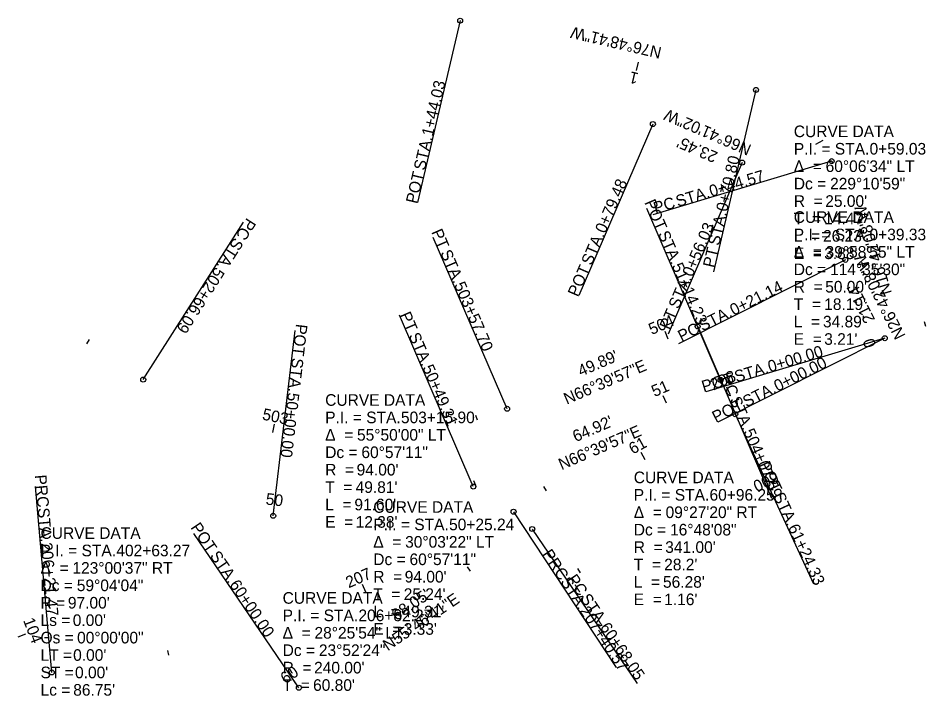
# Model space of a CAD drawing. Extents: x 1600023 to 1602131, y 285824 to 287284.
# Drawn here: x 1601005.3 to 1601224.1, y 286686.3 to 286849.7 of the extents above; entities that cross this region are included whole.
import ezdxf

# ---------------------------------------------------------------- set-up
doc = ezdxf.new("R2010")
doc.units = 0
for name, color, linetype in [('_CIVIL_CONSTRUCTION', 7, 'Continuous'), ('Default', 7, 'Continuous'), ('GE_P_Alignment', 7, 'Continuous'), ('PF_P_Grade_Line', 7, 'Continuous'), ('PF_X_Ground_Line', 7, 'Continuous'), ('SC_Scratch6', 7, 'Continuous'), ('SC_Scratch7', 7, 'Continuous')]:
    doc.layers.add(name, color=color, linetype=linetype)

msp = doc.modelspace()

# ---------------------------------------------------------------- linework, layer by layer
at = {"layer": '_CIVIL_CONSTRUCTION'}
for p, q in [((1601158.26, 286824.15), (1601140.44, 286782.82)), ((1601179.79, 286814.87), (1601161.98, 286773.54)), ((1601204.67, 286791.42), (1601164.47, 286771.2)), ((1601214.17, 286772.53), (1601173.96, 286752.31)), ((1601013.35, 286691.95), (1601009.45, 286736.78)), ((1601124.67, 286730.7), (1601149.45, 286693.13))]:
    msp.add_line(p, q, dxfattribs=at)
for centre in [(1601158.26, 286824.15), (1601179.79, 286814.87), (1601204.67, 286791.42), (1601214.17, 286772.53), (1601124.67, 286730.7), (1601013.35, 286691.95)]:
    msp.add_circle(centre, 0.6, dxfattribs=at)
at = {"layer": 'Default'}
for p, q in [((1601174.59, 286762.47), (1601156.77, 286803.79)), ((1601035.4, 286762.56), (1601059.57, 286800.51)), ((1601123.13, 286755.52), (1601105.31, 286796.84)), ((1601208.96, 286789.65), (1601208.62, 286790.8)), ((1601114.98, 286736.76), (1601097.15, 286778.08)), ((1601169.07, 286775.34), (1601186.88, 286734.01)), ((1601066.74, 286729.72), (1601072.01, 286774.41)), ((1601161.98, 286772.28), (1601161.19, 286774.12)), ((1601021.82, 286771.2), (1601022.47, 286772.22)), ((1601161.52, 286756.84), (1601160.73, 286758.67)), ((1601115.95, 286752.77), (1601115.57, 286753.9)), ((1601178.12, 286754.21), (1601196.97, 286713.35)), ((1601066.63, 286749.83), (1601067.04, 286751.79)), ((1601156.41, 286743.24), (1601155.45, 286745)), ((1601183.71, 286741.37), (1601184.55, 286739.56)), ((1601115.61, 286737.03), (1601115.14, 286738.13)), ((1601066.74, 286729.72), (1601066.98, 286731.7)), ((1601129.19, 286726.54), (1601154.5, 286689.33)), ((1601072.92, 286688.27), (1601047.62, 286725.48)), ((1601114.27, 286716.39), (1601113.59, 286717.38)), ((1601140.1, 286717), (1601140.77, 286716)), ((1601072.92, 286688.27), (1601071.8, 286689.92))]:
    msp.add_line(p, q, dxfattribs=at)
for centre in [(1601169.07, 286775.34), (1601035.4, 286762.56), (1601174.59, 286762.47), (1601123.13, 286755.52), (1601178.12, 286754.21), (1601114.98, 286736.76), (1601066.74, 286729.72), (1601129.19, 286726.54), (1601072.92, 286688.27)]:
    msp.add_circle(centre, 0.6, dxfattribs=at)
at = {"layer": 'SC_Scratch6'}
for p, q in [((1601224.07, 286775.34), (1601223.76, 286776.5)), ((1601176.89, 286758.93), (1601176.09, 286760.77)), ((1601132.62, 286735.78), (1601131.99, 286736.8)), ((1601089.09, 286711.32), (1601088.28, 286713.15)), ((1601005.25, 286700.58), (1601007.12, 286701.3)), ((1601041.56, 286696.1), (1601041.31, 286697.28))]:
    msp.add_line(p, q, dxfattribs=at)
at = {"layer": 'SC_Scratch7'}
for p, q in [((1601111.81, 286849.09), (1601101.55, 286805.27)), ((1601154.68, 286839.04), (1601154.23, 286837.09)), ((1601183.12, 286832.38), (1601172.85, 286788.57)), ((1601199.25, 286820.22), (1601197.5, 286819.24)), ((1601201.36, 286815.22), (1601158.26, 286802.29)), ((1601214.17, 286772.53), (1601171.06, 286759.6)), ((1601214.17, 286772.53), (1601212.25, 286771.96))]:
    msp.add_line(p, q, dxfattribs=at)
for centre in [(1601111.81, 286849.09), (1601183.12, 286832.38), (1601201.36, 286815.22), (1601214.17, 286772.53)]:
    msp.add_circle(centre, 0.6, dxfattribs=at)

# ---------------------------------------------------------------- texts
at = {"layer": '_CIVIL_CONSTRUCTION'}
for s, rotation, p in [('0+79.48', 66.684, (1601146.78, 286797.63)), ('0+56.03', 66.684, (1601167.79, 286787.12)), (' STA. ', 66.684, (1601143.04, 286788.95)), ('POT', 66.684, (1601140.19, 286782.33)), (' STA. ', 66.684, (1601164.04, 286778.44)), ('0+21.14', 26.7021, (1601177.72, 286777.91)), ('PT', 66.684, (1601162.3, 286774.39)), (' STA. ', 26.7021, (1601169.27, 286773.66)), ('PC', 26.7021, (1601165.18, 286771.6)), ('0+00.00', 26.7021, (1601188.32, 286759.58)), (' STA. ', 26.7021, (1601179.88, 286755.33)), ('POT', 26.7021, (1601173.44, 286752.1)), ('PRC', 274.977, (1601009.25, 286739.51)), (' STA. ', 274.977, (1601009.85, 286732.59)), ('206+21.47', 274.977, (1601010.67, 286723.18)), ('PRC', 303.4087, (1601131.46, 286720.49)), (' STA. ', 303.4087, (1601135.28, 286714.69)), ('207+40.57', 303.4087, (1601140.49, 286706.8))]:
    msp.add_text(s, height=2.8, rotation=rotation, dxfattribs=at).set_placement(p)
at = {"layer": 'Default'}
for s, rotation, p in [('POT', 293.3341, (1601156.17, 286805.28)), ('PC', 237.5008, (1601060.4, 286801.72)), ('PT', 293.3341, (1601104.79, 286798.15)), (' STA. ', 237.5008, (1601057.93, 286797.85)), (' STA. ', 293.3341, (1601159.02, 286798.67)), (' STA. ', 293.3341, (1601106.54, 286794.1)), ('51+14.23', 293.3341, (1601162.76, 286789.99)), ('502+66.09', 237.5008, (1601052.85, 286789.88)), ('503+57.70', 293.3341, (1601110.28, 286785.42)), ('PT', 293.3341, (1601097.16, 286778.18)), ('504', 23.3341, (1601157.98, 286773.28)), ('POT', 263.2777, (1601072.25, 286776.07)), (' STA. ', 293.3341, (1601098.9, 286774.13)), ("49.89'", 23.3341, (1601140.92, 286763.24)), (' STA. ', 263.2777, (1601071.41, 286768.92)), ('50+49.31', 293.3341, (1601102.65, 286765.45)), ('N66°39\'57"E', 23.3341, (1601137.51, 286756.5)), ('PC', 293.3233, (1601174.46, 286762.92)), ('51', 23.3341, (1601158.66, 286758.33)), ('50+00.00', 263.2777, (1601070.3, 286759.53)), (' STA. ', 293.3233, (1601176.28, 286758.71)), ('503', 348.167, (1601063.94, 286752.95)), ("64.92'", 23.3341, (1601139.66, 286747.45)), ('N66°39\'57"E', 23.3341, (1601136.25, 286740.71)), ('504+07.59', 293.3233, (1601180.02, 286750.03)), ('61', 28.8536, (1601153.43, 286744.45)), ('POT', 294.7663, (1601183.77, 286742.07)), ('600', 204.8197, (1601187.8, 286740.51)), (' STA. ', 294.7663, (1601186.79, 286735.53)), ('50', 353.2777, (1601064.82, 286732.46)), ('POT', 304.2219, (1601046.71, 286726.89)), ('61+24.33', 294.7663, (1601190.75, 286726.95)), (' STA. ', 304.2219, (1601050.76, 286720.94)), ('PC', 304.2219, (1601137.48, 286714.43)), ('60+00.00', 304.2219, (1601056.07, 286713.12)), ("68.05'", 34.2219, (1601096.44, 286704.31)), ('N55°46\'41"E', 34.2219, (1601094.36, 286697.04)), (' STA. ', 304.2219, (1601140.06, 286710.64)), ('60+68.05', 304.2219, (1601145.37, 286702.83)), ('60', 34.2219, (1601069.68, 286689.08))]:
    msp.add_text(s, height=2.8, rotation=rotation, dxfattribs=at).set_placement(p)
for s, p in [('CURVE DATA', (1601079.27, 286756.24)), ('P.I. = STA. ', (1601079.27, 286752.04)), ('503+15.90', (1601097.53, 286752.04)), ('Δ  = ', (1601079.27, 286747.84)), ('55°50\'00" LT', (1601086.94, 286747.84)), ('Dc = ', (1601079.27, 286743.64)), ('60°57\'11"', (1601088, 286743.64)), ('R  = ', (1601079.27, 286739.44)), ("94.00'", (1601086.85, 286739.44)), ('CURVE DATA', (1601153.66, 286737.58)), ('T  = ', (1601079.27, 286735.24)), ("49.81'", (1601086.6, 286735.24)), ('P.I. = STA. ', (1601153.66, 286733.38)), ('60+96.25', (1601171.92, 286733.38)), ('L  = ', (1601079.27, 286731.04)), ("91.60'", (1601086.31, 286731.04)), ('CURVE DATA', (1601090.86, 286730.44)), ('Δ  = ', (1601153.66, 286729.18)), ('09°27\'20" RT', (1601161.33, 286729.18)), ('E  = ', (1601079.27, 286726.84)), ("12.38'", (1601086.61, 286726.84)), ('P.I. = STA. ', (1601090.86, 286726.24)), ('50+25.24', (1601109.13, 286726.24)), ('CURVE DATA', (1601010.65, 286724.16)), ('Dc = ', (1601153.66, 286724.98)), ('16°48\'08"', (1601162.4, 286724.98)), ('Δ  = ', (1601090.86, 286722.04)), ('30°03\'22" LT', (1601098.54, 286722.04)), ('P.I. = STA. ', (1601010.65, 286719.96)), ('402+63.27', (1601028.92, 286719.96)), ('R  = ', (1601153.66, 286720.78)), ("341.00'", (1601161.24, 286720.78)), ('Dc = ', (1601090.86, 286717.84)), ('60°57\'11"', (1601099.6, 286717.84)), ('Δ  = ', (1601010.65, 286715.76)), ('123°00\'37" RT', (1601018.33, 286715.76)), ('T  = ', (1601153.66, 286716.58)), ("28.2'", (1601160.99, 286716.58)), ('R  = ', (1601090.86, 286713.64)), ("94.00'", (1601098.44, 286713.64)), ('Dc = ', (1601010.65, 286711.56)), ('59°04\'04"', (1601019.39, 286711.56)), ('L  = ', (1601153.66, 286712.38)), ("56.28'", (1601160.7, 286712.38)), ('T  = ', (1601090.86, 286709.44)), ("25.24'", (1601098.2, 286709.44)), ('R = ', (1601010.65, 286707.36)), ("97.00'", (1601017.24, 286707.36)), ('E  = ', (1601153.66, 286708.18)), ("1.16'", (1601161, 286708.18)), ('L  = ', (1601090.86, 286705.24)), ("49.31'", (1601097.9, 286705.24)), ('Ls = ', (1601010.65, 286703.16)), ("0.00'", (1601018.42, 286703.16)), ('E  = ', (1601090.86, 286701.04)), ("3.33'", (1601098.2, 286701.04)), ('Θs = ', (1601010.65, 286698.96)), ('00°00\'00"', (1601019.46, 286698.96)), ('LT = ', (1601010.65, 286694.76)), ("0.00'", (1601018.51, 286694.76)), ('ST = ', (1601010.65, 286690.56)), ("0.00'", (1601018.96, 286690.56)), ('Lc = ', (1601010.65, 286686.36)), ("86.75'", (1601018.53, 286686.36))]:
    msp.add_text(s, height=2.8, dxfattribs=at).set_placement(p)
at = {"layer": 'GE_P_Alignment'}
for s, rotation, p in [('N66°41\'02"W', 156.684, (1601182.23, 286819.04)), ('N26°42\'08"W', 116.7021, (1601219.24, 286773.13))]:
    msp.add_text(s, height=2.8, rotation=rotation, dxfattribs=at).set_placement(p)
at = {"layer": 'PF_P_Grade_Line'}
for s, rotation, p in [("23.45'", 156.684, (1601174.11, 286817.27)), ("21.14'", 116.7021, (1601211.9, 286777))]:
    msp.add_text(s, height=2.8, rotation=rotation, dxfattribs=at).set_placement(p)
at = {"layer": 'PF_X_Ground_Line'}
for s, p in [('CURVE DATA', (1601192.23, 286800.34)), ('P.I. = STA. ', (1601192.23, 286796.14)), ('0+39.33', (1601210.49, 286796.14)), ('Δ  = ', (1601192.23, 286791.94)), ('39°58\'55" LT', (1601199.9, 286791.94)), ('Dc = ', (1601192.23, 286787.74)), ('114°35\'30"', (1601200.97, 286787.74)), ('R  = ', (1601192.23, 286783.54)), ("50.00'", (1601199.81, 286783.54)), ('T  = ', (1601192.23, 286779.34)), ("18.19'", (1601199.57, 286779.34)), ('L  = ', (1601192.23, 286775.14)), ("34.89'", (1601199.27, 286775.14)), ('E  = ', (1601192.23, 286770.94)), ("3.21'", (1601199.57, 286770.94)), ('CURVE DATA', (1601069.01, 286708.52)), ('P.I. = STA. ', (1601069.01, 286704.32)), ('206+82.27', (1601087.28, 286704.32)), ('Δ  = ', (1601069.01, 286700.12)), ('28°25\'54" LT', (1601076.69, 286700.12)), ('Dc = ', (1601069.01, 286695.92)), ('23°52\'24"', (1601077.75, 286695.92)), ('R  = ', (1601069.01, 286691.72)), ("240.00'", (1601076.59, 286691.72)), ('T  = ', (1601069.01, 286687.52)), ("60.80'", (1601076.35, 286687.52))]:
    msp.add_text(s, height=2.8, dxfattribs=at).set_placement(p)
at = {"layer": 'SC_Scratch6'}
for s, rotation, p in [('208', 23.393, (1601172.83, 286759.9)), ('207', 23.7245, (1601084.96, 286712.24)), ('104', 290.9948, (1601006.41, 286704.53))]:
    msp.add_text(s, height=2.8, rotation=rotation, dxfattribs=at).set_placement(p)
at = {"layer": 'SC_Scratch7'}
for s, rotation, p in [('N76°48\'41"W', 166.8115, (1601160.55, 286842.6)), ('1', 166.8115, (1601155, 286836.4)), ('1+44.03', 76.8115, (1601105.19, 286821.02)), (' STA. ', 76.8115, (1601103.04, 286811.82)), ('0+70.80', 76.8115, (1601176.16, 286802.88)), ('POT', 76.8115, (1601101.39, 286804.81)), ('0+44.57', 16.7021, (1601172.33, 286806.56)), (' STA. ', 16.7021, (1601163.28, 286803.84)), ('PC', 16.7021, (1601158.89, 286802.52)), ('N16°42\'08"W', 106.7021, (1601215.9, 286783.46)), (' STA. ', 76.8115, (1601174, 286793.68)), ('PT', 76.8115, (1601173, 286789.38)), ('0+00.00', 16.7021, (1601186.46, 286764.27)), ('0', 106.7021, (1601212.09, 286770.75)), (' STA. ', 16.7021, (1601177.41, 286761.55)), ('POT', 16.7021, (1601170.51, 286759.48))]:
    msp.add_text(s, height=2.8, rotation=rotation, dxfattribs=at).set_placement(p)
for s, p in [('CURVE DATA', (1601192.24, 286821)), ('P.I. = STA. ', (1601192.24, 286816.8)), ('0+59.03', (1601210.5, 286816.8)), ('Δ  = ', (1601192.24, 286812.6)), ('60°06\'34" LT', (1601199.91, 286812.6)), ('Dc = ', (1601192.24, 286808.4)), ('229°10\'59"', (1601200.98, 286808.4)), ('R  = ', (1601192.24, 286804.2)), ("25.00'", (1601199.82, 286804.2)), ('T  = ', (1601192.24, 286800)), ("14.47'", (1601199.57, 286800)), ('L  = ', (1601192.24, 286795.8)), ("26.23'", (1601199.28, 286795.8)), ('E  = ', (1601192.24, 286791.6)), ("3.88'", (1601199.58, 286791.6))]:
    msp.add_text(s, height=2.8, dxfattribs=at).set_placement(p)

doc.saveas('drawing.dxf')
